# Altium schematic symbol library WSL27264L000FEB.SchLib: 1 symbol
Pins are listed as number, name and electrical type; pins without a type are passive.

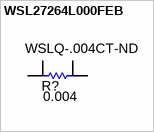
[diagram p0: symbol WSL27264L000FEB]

## WSL27264L000FEB
designator R?  ValueDisplayed: 0.004  Supplier Part Number: WSLQ-.004CT-ND  (hidden comment: WSL27264L000FEB)
RES SMD 0.004 OHM 1% 3W 2726; Manufacturer: Vishay Dale; CompType: Resistor; Value: 0.004; Res_ohm: 0.001; Value_Code: 1L000; TempCo: ±75ppm/°C; EIA_Code: E96; U/M: EA
signal-integrity model Resistor
simulation model Resistor
footprint RES_WSL2726
footprint RES_WSL2726 WITH VIAS (Vishay Dale)
pins: 1, 2, 3, 4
